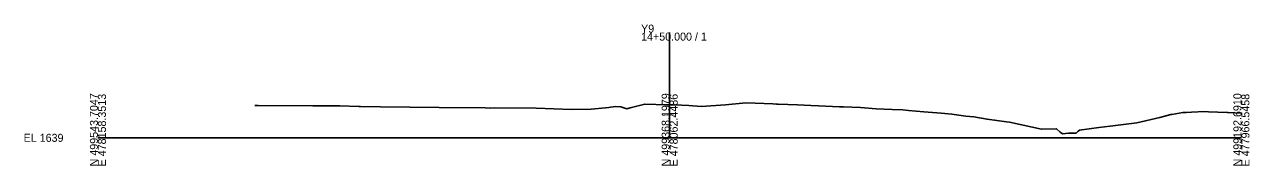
# Model space of a CAD drawing. Extents: x -26 to 403, y -99 to 4540.
# Drawn here: x -25.7 to 402.8, y 4490.3 to 4539.7 of the extents above; entities that cross this region are included whole.
import ezdxf

# ---------------------------------------------------------------- set-up
doc = ezdxf.new("R2010")
doc.units = 0
for name, color, linetype in [('Exist Cross Section Cell', 7, 'Continuous'), ('Exist XS Center Line Elevation Label', 7, 'Continuous'), ('Exist XS Ground Line', 7, 'Continuous')]:
    doc.layers.add(name, color=color, linetype=linetype)

msp = doc.modelspace()

# ---------------------------------------------------------------- linework, layer by layer
at = {"layer": 'Exist Cross Section Cell'}
for p, q in [((200, 4500), (200, 4536.84)), ((0, 4500), (200, 4500)), ((200, 4500), (400, 4500))]:
    msp.add_line(p, q, dxfattribs=at)
at = {"layer": 'Exist XS Ground Line'}
msp.add_lwpolyline([(54.83, 4511.35), (56.05, 4511.35), (75.12, 4511.18), (83.6, 4511.15), (84.62, 4511.17), (91.21, 4510.97), (91.86, 4510.96), (98.8, 4510.83), (119.32, 4510.65), (135.48, 4510.46), (137.43, 4510.44), (138.82, 4510.45), (153.26, 4510.38), (165.64, 4509.88), (172.59, 4510.08), (177.6, 4510.54), (178.75, 4510.62), (179.33, 4510.71), (181.21, 4510.99), (182.93, 4510.84), (185.02, 4510.11), (186.14, 4510.48), (191.31, 4511.79), (199.18, 4511.55), (200, 4511.52), (204.18, 4511.4), (206.75, 4511.27), (211.02, 4510.99), (219.58, 4511.61), (226.61, 4512.22), (229.96, 4512.19), (236.09, 4511.91), (237.33, 4511.78), (238.01, 4511.79), (244.7, 4511.53), (249.4, 4511.28), (252.07, 4511.15), (256.95, 4510.93), (259.44, 4510.8), (260.8, 4510.8), (266.81, 4510.64), (272.2, 4510.16), (277.81, 4509.87), (281.55, 4509.78), (283.6, 4509.62), (288.92, 4509.14), (295, 4508.62), (296.29, 4508.5), (298.67, 4508.24), (303.66, 4507.59), (306.39, 4507.35), (311.03, 4506.5), (317.79, 4505.59), (318.83, 4505.45), (330.06, 4503.02), (335.33, 4503.19), (336.55, 4501.95), (337.43, 4501.43), (339.58, 4501.6), (342.17, 4501.58), (342.94, 4502.29), (343.42, 4502.73), (350.11, 4503.57), (354.07, 4504.09), (363.38, 4505.22), (371.43, 4507.06), (375.36, 4508.19), (375.71, 4508.22), (379.53, 4508.87), (380.71, 4508.84), (382.5, 4508.93), (387.1, 4509.17), (388.44, 4509.16), (395.01, 4508.9), (395.34, 4508.9), (400, 4508.68)], dxfattribs=at)

# ---------------------------------------------------------------- texts
at = {"layer": 'Exist Cross Section Cell'}
for s, p in [('Y9', (190, 4536.84)), ('14+50.000 / 1', (190, 4534.04)), ('EL 1639', (-26, 4498.6))]:
    msp.add_text(s, height=2.8, dxfattribs=at).set_placement(p)
for s, p in [('N 499543.7047', (0, 4490)), ('E 478158.3513', (2.8, 4490)), ('N 499368.1979', (200, 4490)), ('E 478062.4486', (202.8, 4490)), ('N 499192.6910', (400, 4490)), ('E 477966.5458', (402.8, 4490))]:
    msp.add_text(s, height=2.8, rotation=90, dxfattribs=at).set_placement(p)
at = {"layer": 'Exist XS Center Line Elevation Label'}
msp.add_text('1650.52', height=0.9, dxfattribs=at).set_placement((197.84, 4507.62))

doc.saveas('drawing.dxf')
